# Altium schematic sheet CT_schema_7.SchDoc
size 368 x 245 mm
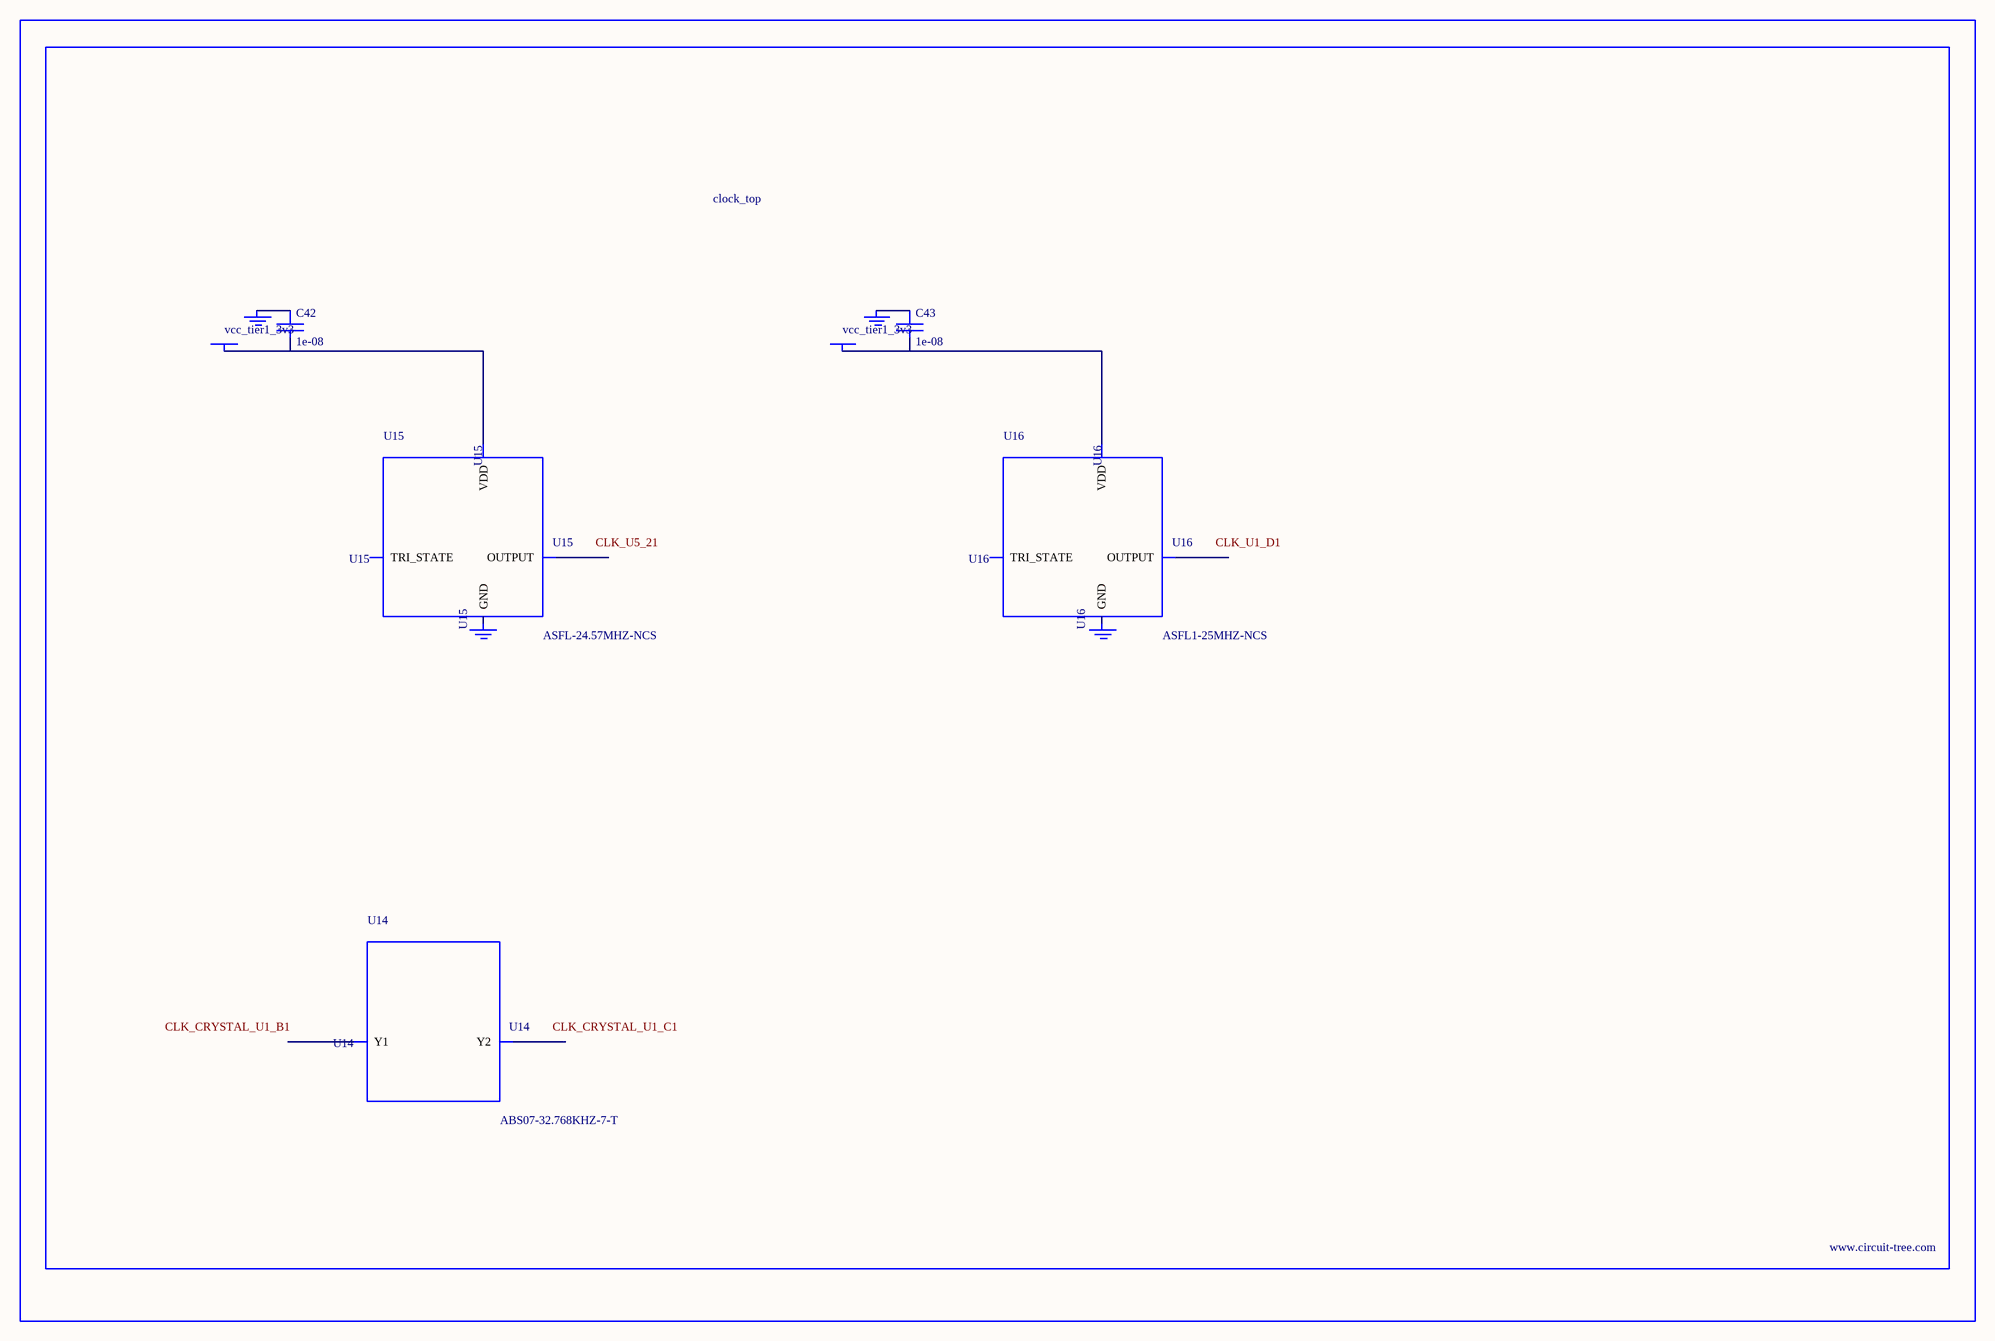
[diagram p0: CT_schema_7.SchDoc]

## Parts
BORDER6  (no value)
C42  1e-08  [C0402]
C43  1e-08  [C0402]
GND_INSTANCE_6_0  (no value)
GND_INSTANCE_6_1  (no value)
GND_INSTANCE_6_2  (no value)
GND_INSTANCE_6_3  (no value)
POWER_INSTANCE_6_0  vcc_tier1_3v3
POWER_INSTANCE_6_1  vcc_tier1_3v3
U14  ABS07-32.768KHZ-7-T  [ABS07-32.768KHZ-7-T]
U15  ASFL-24.57MHZ-NCS  [ASFL1]
U16  ASFL1-25MHZ-NCS  [ASFL1]

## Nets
NetC42_1: C42.1 GND_INSTANCE_6_0.0(GND)
NetC42_2: C42.2 POWER_INSTANCE_6_0.0(PWR) U15.4(VDD)
NetC43_1: C43.1 GND_INSTANCE_6_2.0(GND)
NetC43_2: C43.2 POWER_INSTANCE_6_1.0(PWR) U16.4(VDD)

Not connected (* = marked no-connect by the designer): GND_INSTANCE_6_1 0(GND); GND_INSTANCE_6_3 0(GND); U14 1(Y1) 2(Y2); U15 1(TRI_STATE) 2(GND) 3(OUTPUT); U16 1(TRI_STATE) 2(GND) 3(OUTPUT)

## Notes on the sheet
- Labels drawn without touching a wire or pin: CLK_CRYSTAL_U1_B1, CLK_CRYSTAL_U1_C1, CLK_U1_D1, CLK_U5_21

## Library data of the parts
BORDER6 = BORDER_PAGE6
C42 C43 = C0402C103K3RAC
GND_INSTANCE_6_0-GND_INSTANCE_6_3 = GND
POWER_INSTANCE_6_0 POWER_INSTANCE_6_1 = PWR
